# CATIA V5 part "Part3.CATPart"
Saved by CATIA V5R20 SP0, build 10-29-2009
Part number: Part3
Bounding box of the stored display mesh (mm): x -2 to 3, y -20 to 20, z -20 to 20
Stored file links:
  C:\Users\12584\Desktop\新建文件夹 (3)\Part3.CATPart
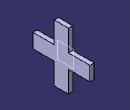
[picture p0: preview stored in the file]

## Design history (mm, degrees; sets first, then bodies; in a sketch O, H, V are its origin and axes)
Body1 (main body)
  Sketch1 on yz-plane, origin (0, 0, 0), H (0, 1, 0), V (0, 0, 1)
    line L1 (-20, 5) -> (-5, 5)
    line L2 (20, 5) -> (20, -5)
    line L3 (20, -5) -> (5, -5)
    line L4 (-20, -5) -> (-20, 5)
    line L5 (-5, 20) -> (5, 20)
    line L6 (5, 20) -> (5, 5)
    line L7 (5, -20) -> (-5, -20)
    line L8 (-5, -20) -> (-5, -5)
    point P9 (-5, 5)
    line L9 (5, 5) -> (20, 5)
    line L10 (5, -5) -> (5, -20)
    line L11 (-5, 5) -> (-5, 20)
    point P12 (-5, -5)
    line L12 (-5, -5) -> (-20, -5)
    length L2 = 10
    length L5 = 10
    distance V L11 = 5
    distance H L3 = 5
    horizontal: L1 H, L3 H, L5 H, L7 H, L9 H, L12 H
    vertical: L2 V, L4 V, L6 V, L8 V, L10 V, L11 V
    coincidence: L8 P9, L1 L9, L6 L10, L3 P12, L8 L11, L3 L12
  Pad1: profile Sketch1, direction (1, 0, 0), length 3
  Sketch2 on yz-plane, origin (0, 0, 0), H (0, 1, 0), V (0, 0, 1)
    circle A1 centre (0, 0) radius 2.5
    radius A1 = 2.5
  Pad2: profile Sketch2, direction (-1, 0, 0), length 2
